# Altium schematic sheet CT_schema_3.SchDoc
size 289 x 159 mm
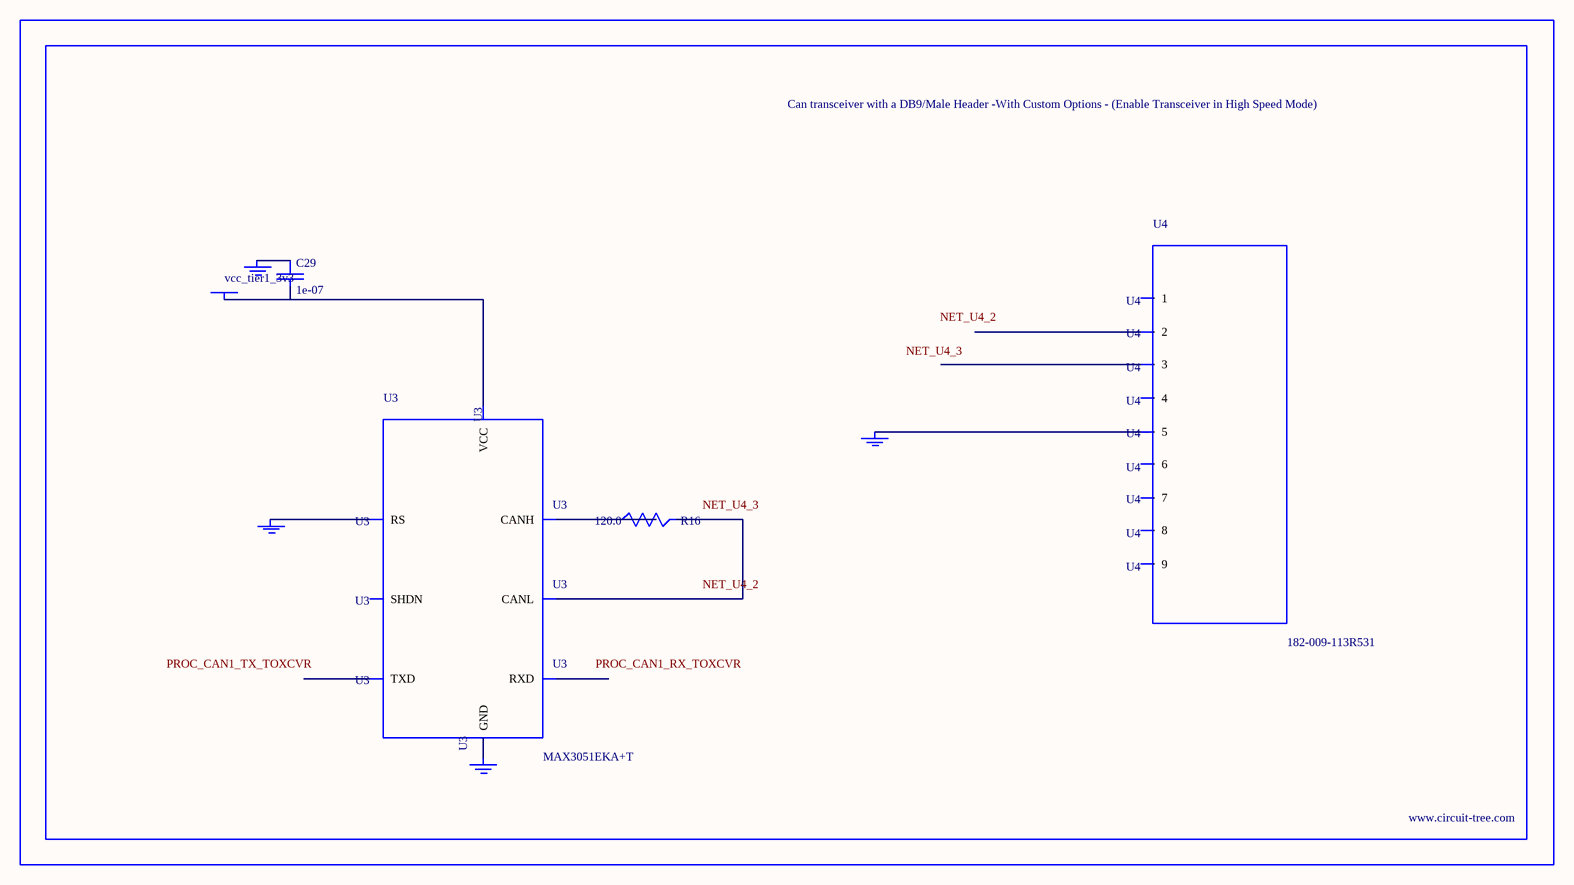
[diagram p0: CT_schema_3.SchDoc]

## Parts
BORDER2  (no value)
C29  1e-07  [C0402]
GND_INSTANCE_2_0  (no value)
GND_INSTANCE_2_1  (no value)
GND_INSTANCE_2_2  (no value)
GND_INSTANCE_2_3  (no value)
POWER_INSTANCE_2_0  vcc_tier1_3v3
R16  120.0  [R0603]
U3  MAX3051EKA+T  [SOT-23-8]
U4  182-009-113R531  [182-009-MALE]

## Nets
NetC29_1: C29.1 GND_INSTANCE_2_0.0(GND)
NetC29_2: C29.2 POWER_INSTANCE_2_0.0(PWR) U3.3(VCC)
NetGND_INSTANCE_2_1_0: GND_INSTANCE_2_1.0(GND) U3.8(RS)
NetGND_INSTANCE_2_2_0: GND_INSTANCE_2_2.0(GND) U3.2(GND)
NetGND_INSTANCE_2_3_0: GND_INSTANCE_2_3.0(GND) U4.5
NetR16_1: R16.1 U3.7(CANH)
NetR16_2: R16.2 U3.6(CANL)

Not connected (* = marked no-connect by the designer): U3 1(TXD) 4(RXD) 5(SHDN); U4 1 2 3 4 6 7 8 9

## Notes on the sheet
- Labels drawn without touching a wire or pin: NET_U4_2, NET_U4_3, PROC_CAN1_RX_TOXCVR, PROC_CAN1_TX_TOXCVR

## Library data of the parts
BORDER2 = BORDER_PAGE2
C29 = C0402C104K3RACTU
GND_INSTANCE_2_0-GND_INSTANCE_2_3 = GND
POWER_INSTANCE_2_0 = PWR
R16 = RC0603JR-07120RL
